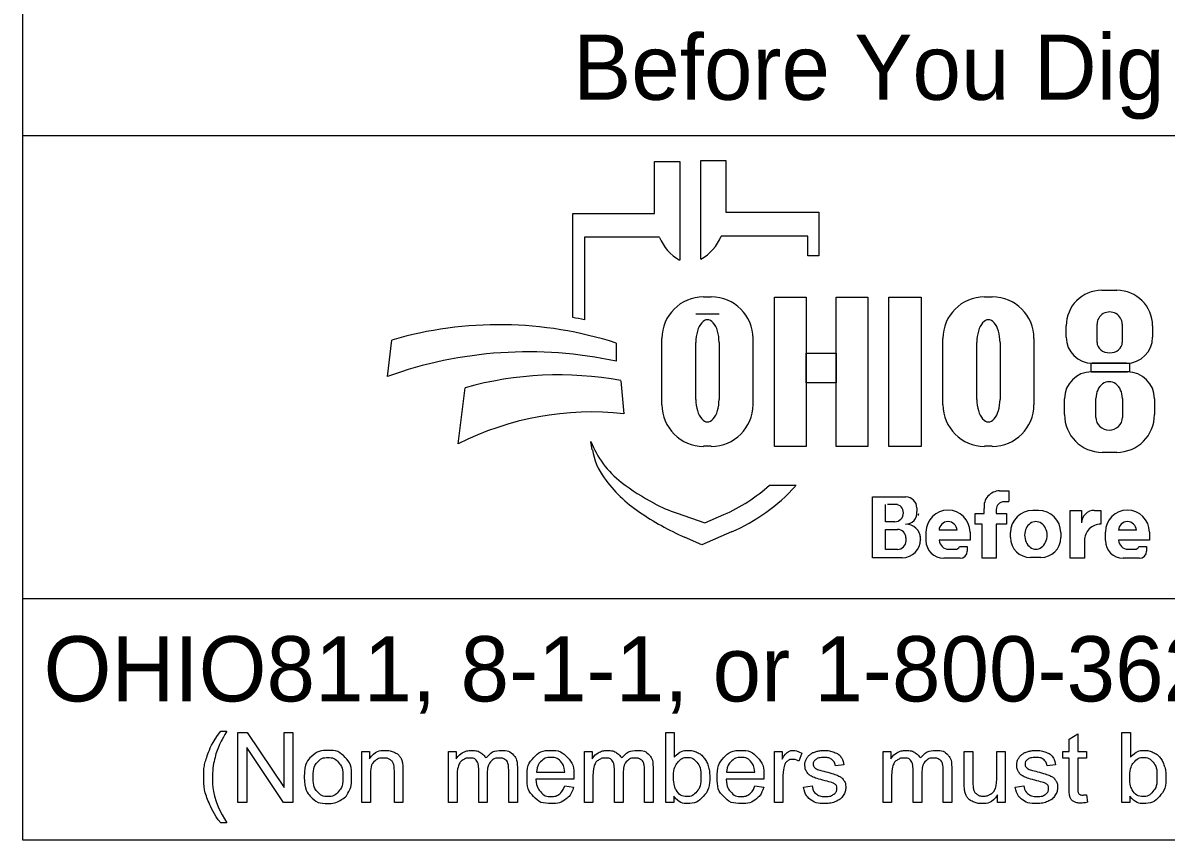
# Model space of a CAD drawing. Extents: x -10 to 89.7, y -4.8 to 22.
# Drawn here: x 2.978 to 5.431, y 2.143 to 3.897 of the extents above; entities that cross this region are included whole.
import ezdxf

# ---------------------------------------------------------------- set-up
doc = ezdxf.new("R2010")
doc.units = 0
doc.layers.add('GM_X_Minor_Lake', color=7, linetype='Continuous')
doc.layers.add('GM_X_Minor_River_Text', color=7, linetype='Continuous')

msp = doc.modelspace()

# ---------------------------------------------------------------- linework, layer by layer
at = {"layer": 'GM_X_Minor_Lake'}
for p, q in [((2.9775, 2.1428), (2.9775, 4.4803)), ((2.9775, 3.6553), (7.2275, 3.6553)), ((7.2275, 2.6607), (2.9775, 2.6607)), ((7.2275, 2.1428), (2.9775, 2.1428))]:
    msp.add_line(p, q, dxfattribs=at)
at = {"layer": 'GM_X_Minor_River_Text'}
for p, q in [((4.3335, 3.4883), (4.3335, 3.5998)), ((4.3335, 3.5998), (4.3872, 3.5998)), ((4.3872, 3.5998), (4.3872, 3.3877)), ((4.4329, 3.39), (4.4329, 3.6021)), ((4.4329, 3.6021), (4.4865, 3.6021)), ((4.4865, 3.6021), (4.4865, 3.4906)), ((4.1576, 3.2644), (4.1576, 3.4883)), ((4.1576, 3.4883), (4.3335, 3.4883)), ((4.4865, 3.4906), (4.6857, 3.4906)), ((4.6857, 3.4906), (4.6857, 3.3968)), ((4.1828, 3.4369), (4.1828, 3.26)), ((4.3439, 3.4369), (4.1828, 3.4369)), ((4.6625, 3.4392), (4.4761, 3.4392)), ((4.6625, 3.3968), (4.6625, 3.4392)), ((4.6857, 3.3968), (4.6625, 3.3968)), ((5.2931, 3.3231), (5.3258, 3.3231)), ((4.4385, 3.3091), (4.4551, 3.3091)), ((5.0416, 3.3091), (5.0581, 3.3091)), ((4.4718, 3.2721), (4.422, 3.2721)), ((5.2168, 3.2225), (5.2168, 3.2468)), ((5.283, 3.2111), (5.283, 3.2504)), ((5.3371, 3.2504), (5.3371, 3.2111)), ((5.4022, 3.2468), (5.4022, 3.2225)), ((3.7602, 3.1381), (3.7696, 3.2162)), ((4.3491, 3.0776), (4.3491, 3.2196)), ((4.5445, 3.2196), (4.5445, 3.0776)), ((4.9521, 3.0776), (4.9521, 3.2196)), ((5.1476, 3.2196), (5.1476, 3.0776)), ((4.2509, 3.2097), (4.2509, 3.1709)), ((4.422, 3.089), (4.422, 3.2114)), ((4.4718, 3.2114), (4.4718, 3.089)), ((5.025, 3.089), (5.025, 3.2114)), ((5.0748, 3.2114), (5.0748, 3.089)), ((5.3462, 3.1665), (5.2728, 3.1665)), ((5.271, 3.1482), (5.3483, 3.1482)), ((4.2608, 3.1291), (4.2671, 3.0582)), ((3.912, 2.9936), (3.9267, 3.1137)), ((5.2131, 3.0563), (5.2131, 3.0903)), ((5.2806, 3.0503), (5.2806, 3.0912)), ((5.3374, 3.0912), (5.3374, 3.0503)), ((5.4062, 3.0903), (5.4062, 3.0563)), ((4.1997, 2.9807), (4.1967, 2.9986)), ((4.4551, 2.9882), (4.4385, 2.9882)), ((5.0581, 2.9882), (5.0416, 2.9882)), ((5.3252, 2.9753), (5.2941, 2.9753)), ((4.58, 2.9048), (4.6375, 2.9048)), ((4.8013, 2.749), (4.8013, 2.8798)), ((4.8013, 2.8798), (4.8725, 2.8798)), ((5.0739, 2.8926), (5.0934, 2.8926)), ((5.0934, 2.8926), (5.0934, 2.8696)), ((4.8293, 2.8263), (4.8293, 2.8632)), ((4.8545, 2.8632), (4.8332, 2.8632)), ((4.8963, 2.856), (4.8963, 2.8481)), ((5.0406, 2.8442), (5.0406, 2.8546)), ((5.0667, 2.8526), (5.0667, 2.8442)), ((5.0934, 2.8691), (5.0832, 2.8691)), ((5.1451, 2.8508), (5.1573, 2.8508)), ((5.2254, 2.7478), (5.2254, 2.8505)), ((5.2254, 2.8505), (5.2499, 2.8505)), ((5.2499, 2.8505), (5.2499, 2.8237)), ((5.2772, 2.8505), (5.291, 2.8505)), ((5.291, 2.8505), (5.291, 2.8209)), ((4.3816, 2.8444), (4.441, 2.8239)), ((4.441, 2.8239), (4.4821, 2.8417)), ((4.8487, 2.8263), (4.8293, 2.8263)), ((5.0213, 2.8212), (5.0213, 2.8442)), ((5.0213, 2.8442), (5.0406, 2.8442)), ((5.0667, 2.8442), (5.0883, 2.8442)), ((5.0883, 2.8442), (5.0883, 2.8212)), ((4.4983, 2.8044), (4.435, 2.7769)), ((4.8293, 2.7669), (4.8293, 2.8097)), ((4.8293, 2.8097), (4.8548, 2.8097)), ((4.9159, 2.7858), (4.9159, 2.8042)), ((4.9824, 2.8082), (4.9439, 2.8082)), ((5.0104, 2.8042), (5.0104, 2.7866)), ((5.0362, 2.8212), (5.0213, 2.8212)), ((5.0362, 2.7478), (5.0362, 2.8212)), ((5.0883, 2.8212), (5.0667, 2.8212)), ((5.0667, 2.8212), (5.0667, 2.7478)), ((5.0973, 2.7922), (5.0973, 2.8029)), ((5.2051, 2.8029), (5.2051, 2.7922)), ((5.3008, 2.7858), (5.3008, 2.8042)), ((5.3674, 2.8082), (5.3288, 2.8082)), ((5.3953, 2.8042), (5.3953, 2.7866)), ((4.435, 2.7769), (4.3976, 2.7934)), ((4.8729, 2.7916), (4.8729, 2.7853)), ((4.9043, 2.7887), (4.9043, 2.7884)), ((5.0104, 2.7866), (4.944, 2.7866)), ((4.9876, 2.7729), (5.0045, 2.7729)), ((5.0045, 2.7729), (5.0045, 2.7631)), ((5.2559, 2.786), (5.2559, 2.7478)), ((5.3953, 2.7866), (5.3289, 2.7866)), ((5.3725, 2.7729), (5.3894, 2.7729)), ((5.3894, 2.7729), (5.3894, 2.7631)), ((4.865, 2.749), (4.8013, 2.749)), ((4.8546, 2.7669), (4.8293, 2.7669)), ((4.9649, 2.7673), (4.979, 2.7673)), ((5.1623, 2.7494), (5.1401, 2.7494)), ((5.3498, 2.7673), (5.3639, 2.7673)), ((4.9892, 2.7478), (4.9538, 2.7478)), ((5.0667, 2.7478), (5.0362, 2.7478)), ((5.2559, 2.7478), (5.2254, 2.7478)), ((5.3742, 2.7478), (5.3388, 2.7478))]:
    msp.add_line(p, q, dxfattribs=at)
for points in [[(4.591, 3.3081), (4.6589, 3.3081), (4.6589, 2.9881), (4.591, 2.9881)], [(4.7231, 3.3081), (4.7911, 3.3081), (4.7911, 2.9881), (4.7231, 2.9881)], [(4.8364, 3.3081), (4.9052, 3.3081), (4.9052, 2.9881), (4.8364, 2.9881)], [(4.6589, 3.1882), (4.7231, 3.1882), (4.7231, 3.1242), (4.6589, 3.1242)], [(5.2706, 3.1665), (5.3523, 3.1665), (5.3523, 3.1481), (5.2706, 3.1481)]]:
    msp.add_lwpolyline(points, close=True, dxfattribs=at)
for points in [[(3.4021, 2.3766), (3.4153, 2.3766)], [(3.4389, 2.2239), (3.4389, 2.3741), (3.4592, 2.3741), (3.5382, 2.2561), (3.5382, 2.3741), (3.5572, 2.3741), (3.5572, 2.2239), (3.5369, 2.2239), (3.4579, 2.3419), (3.4579, 2.2239), (3.4389, 2.2239)], [(4.3743, 2.2239), (4.3573, 2.2239), (4.3573, 2.3741), (4.3757, 2.3741), (4.3757, 2.3206)], [(5.2233, 2.2558), (5.2233, 2.3185), (5.2097, 2.3185), (5.2097, 2.3328), (5.2233, 2.3328), (5.2233, 2.3597), (5.2417, 2.3708), (5.2417, 2.3328), (5.2601, 2.3328), (5.2601, 2.3185), (5.2417, 2.3185), (5.2417, 2.2547)], [(5.3534, 2.2239), (5.3363, 2.2239), (5.3363, 2.3741), (5.3548, 2.3741), (5.3548, 2.3206)], [(3.7048, 2.2239), (3.7048, 2.3328), (3.7214, 2.3328), (3.7214, 2.3173)], [(3.8912, 2.2239), (3.8912, 2.3328), (3.9077, 2.3328), (3.9077, 2.3174)], [(4.1826, 2.2239), (4.1826, 2.3328), (4.1991, 2.3328), (4.1991, 2.3174)], [(4.5904, 2.2239), (4.5904, 2.3328), (4.607, 2.3328), (4.607, 2.3163)], [(4.8236, 2.2239), (4.8236, 2.3328), (4.8401, 2.3328), (4.8401, 2.3174)], [(4.9979, 2.2654), (4.9979, 2.3328), (5.0164, 2.3328), (5.0164, 2.2724)], [(5.0676, 2.2745), (5.0676, 2.3328), (5.0861, 2.3328), (5.0861, 2.2239), (5.0696, 2.2239)], [(4.6495, 2.3293), (4.643, 2.3122)], [(3.7233, 2.2833), (3.7233, 2.2239), (3.7048, 2.2239)], [(3.7932, 2.2908), (3.7932, 2.2239), (3.7748, 2.2239), (3.7748, 2.2901)], [(3.9743, 2.2871), (3.9743, 2.2239), (3.9559, 2.2239), (3.9559, 2.2946)], [(4.0388, 2.2986), (4.0388, 2.2239), (4.0203, 2.2239), (4.0203, 2.2924)], [(4.0799, 2.2887), (4.1406, 2.2887)], [(4.2657, 2.2871), (4.2657, 2.2239), (4.2473, 2.2239), (4.2473, 2.2946)], [(4.3301, 2.2986), (4.3301, 2.2239), (4.3117, 2.2239), (4.3117, 2.2924)], [(4.4879, 2.2887), (4.5486, 2.2887)], [(4.7394, 2.3046), (4.7213, 2.3022)], [(4.9067, 2.2871), (4.9067, 2.2239), (4.8883, 2.2239), (4.8883, 2.2946)], [(4.9711, 2.2986), (4.9711, 2.2239), (4.9527, 2.2239), (4.9527, 2.2924)], [(5.194, 2.3046), (5.1759, 2.3022)], [(3.9097, 2.2803), (3.9097, 2.2239), (3.8912, 2.2239)], [(4.16, 2.2736), (4.0788, 2.2736)], [(4.1404, 2.2591), (4.1595, 2.2567)], [(4.201, 2.2803), (4.201, 2.2239), (4.1826, 2.2239)], [(4.568, 2.2736), (4.4868, 2.2736)], [(4.5484, 2.2591), (4.5675, 2.2567)], [(4.6088, 2.2809), (4.6088, 2.2239), (4.5904, 2.2239)], [(4.653, 2.2564), (4.6712, 2.2593)], [(4.842, 2.2803), (4.842, 2.2239), (4.8236, 2.2239)], [(5.1076, 2.2564), (5.1258, 2.2593)], [(4.3743, 2.2375), (4.3743, 2.2239)], [(5.0696, 2.2239), (5.0696, 2.24)], [(5.2601, 2.2404), (5.2628, 2.2241)], [(5.3534, 2.2375), (5.3534, 2.2239)], [(3.4153, 2.1798), (3.4021, 2.1798)]]:
    msp.add_lwpolyline(points, dxfattribs=at)
for centre, radius, start, end in [((4.4353, 3.4736), 0.0985, 201.9296, 240.7469), ((4.3847, 3.476), 0.0985, 299.2531, 338.0704), ((5.2931, 3.2468), 0.0763, 90, 180), ((5.3258, 3.2468), 0.0763, 0, 90), ((4.4385, 3.2196), 0.0895, 90, 180), ((4.4551, 3.2196), 0.0895, 0, 90), ((5.0416, 3.2196), 0.0895, 90, 180), ((5.0581, 3.2196), 0.0895, 0, 90), ((4.0295, 2.4554), 0.8191, 79.2074, 81.0007), ((3.9997, 2.4302), 0.8191, 72.1402, 106.3144), ((5.2728, 3.2225), 0.056, 180, 270), ((5.3462, 3.2225), 0.056, 270, 0), ((4.0628, 2.2991), 0.8919, 77.8238, 109.8274), ((4.1267, 2.4094), 0.7322, 79.44, 105.8467), ((5.271, 3.0903), 0.0579, 90, 180), ((5.3483, 3.0903), 0.0579, 0, 90), ((4.4385, 3.0776), 0.0895, 180, 270), ((4.4551, 3.0776), 0.0895, 270, 0), ((5.0416, 3.0776), 0.0895, 180, 270), ((5.0581, 3.0776), 0.0895, 270, 0), ((4.1987, 2.4262), 0.6357, 83.8248, 116.8021), ((5.2941, 3.0563), 0.081, 180, 270), ((5.3252, 3.0563), 0.081, 270, 0), ((4.3841, 3.0707), 0.2008, 201.0457, 232.5314), ((4.341, 3.0048), 0.1433, 189.6817, 216.0884), ((4.4747, 3.1022), 0.3088, 216.0884, 235.7167), ((4.5766, 3.3219), 0.5173, 232.5314, 241.794), ((4.3387, 3.1722), 0.3602, 293.4582, 312.0712), ((4.3387, 3.1722), 0.401, 293.4582, 317.8286), ((4.8725, 2.856), 0.0238, 0, 90), ((5.0739, 2.859), 0.0335, 90, 187.5187), ((4.6412, 3.3465), 0.6044, 235.7167, 246.2325), ((4.4914, 3.1631), 0.3371, 241.794, 250.9821), ((4.8505, 2.8463), 0.0169, 357.8325, 90), ((4.8721, 2.8453), 0.0243, 270, 6.6529), ((4.9631, 2.8042), 0.0473, 0, 180), ((5.0832, 2.8526), 0.0165, 90, 180), ((5.1451, 2.8029), 0.0478, 90, 180), ((5.1573, 2.8029), 0.0478, 0, 90), ((5.2768, 2.8237), 0.0269, 89.2449, 180), ((5.3481, 2.8042), 0.0473, 0, 180), ((4.8487, 2.845), 0.0187, 270, 2.0582), ((4.8827, 2.8438), 0.0175, 347.4023, 0), ((4.9632, 2.8072), 0.0193, 2.9632, 177.0368), ((5.3481, 2.8072), 0.0193, 2.9632, 177.0368), ((4.8548, 2.7916), 0.0181, 0, 90), ((4.8722, 2.7889), 0.0321, 4.0748, 90), ((5.2908, 2.786), 0.0349, 89.6033, 180), ((4.8546, 2.7853), 0.0184, 270, 0), ((4.865, 2.7884), 0.0393, 270, 0), ((4.8714, 2.7887), 0.033, 0, 11.7502), ((4.9538, 2.7858), 0.038, 180, 270), ((4.9649, 2.7883), 0.021, 184.827, 270), ((4.979, 2.7767), 0.00938, 270, 335.9979), ((5.1401, 2.7922), 0.0428, 180, 270), ((5.1623, 2.7922), 0.0428, 270, 0), ((5.3388, 2.7858), 0.038, 180, 270), ((5.3498, 2.7883), 0.021, 184.827, 270), ((5.3639, 2.7767), 0.00938, 270, 335.9979), ((4.9892, 2.7631), 0.0152, 270, 0), ((5.3742, 2.7631), 0.0152, 270, 0)]:
    msp.add_arc(centre, radius, start, end, dxfattribs=at)
for centre, major_axis, ratio, start_param, end_param in [((5.31, 3.2504), (0.0271, 0), 0.969373, 0, 3.141593), ((4.4469, 3.2114), (0, 0.0484), 0.514403, 4.712389, 7.853982), ((5.0499, 3.2114), (0, 0.0484), 0.514403, 4.712389, 7.853982), ((5.31, 3.2111), (0.0271, 0), 0.818453, 3.141593, 6.283185), ((5.309, 3.0912), (0, 0.0358), 0.794529, 4.712389, 7.853982), ((4.4469, 3.089), (0, 0.0484), 0.514403, 1.570796, 4.712389), ((5.0499, 3.089), (0, 0.0484), 0.514403, 1.570796, 4.712389), ((5.309, 3.0503), (0.0284, 0), 0.959837, 3.141593, 6.283185), ((5.1517, 2.7976), (0, 0.029), 0.832186, 4.712389, 7.853982), ((5.1517, 2.7976), (0, 0.0302), 0.797287, 1.570796, 4.712389)]:
    msp.add_ellipse(centre, major_axis=major_axis, ratio=ratio, start_param=start_param, end_param=end_param, dxfattribs=at)
for points in [[(3.4021, 2.1798), (3.3869, 2.199), (3.3763, 2.2248), (3.3657, 2.2506), (3.3657, 2.2783), (3.3657, 2.3026), (3.3736, 2.325), (3.3829, 2.3509), (3.4021, 2.3766)], [(3.4153, 2.3766), (3.4029, 2.3553), (3.3989, 2.3462), (3.3927, 2.332), (3.3891, 2.3167), (3.3847, 2.2975), (3.3847, 2.2782), (3.3847, 2.2289), (3.4153, 2.1798)], [(3.5814, 2.2783), (3.5814, 2.3085), (3.5981, 2.3231), (3.6122, 2.3352), (3.6323, 2.3352), (3.6547, 2.3352), (3.669, 2.3205), (3.6832, 2.3058), (3.6832, 2.2799), (3.6832, 2.2589), (3.6769, 2.2469), (3.6706, 2.2348), (3.6586, 2.2282), (3.6466, 2.2215), (3.6323, 2.2215), (3.6095, 2.2215), (3.5954, 2.2362), (3.5814, 2.2508), (3.5814, 2.2783)], [(3.7214, 2.3173), (3.7334, 2.3352), (3.756, 2.3352), (3.7659, 2.3352), (3.7741, 2.3316), (3.7823, 2.3281), (3.7864, 2.3224), (3.7905, 2.3166), (3.7922, 2.3087), (3.7932, 2.3036), (3.7932, 2.2908)], [(3.9077, 2.3174), (3.9128, 2.3254), (3.9214, 2.3303), (3.9299, 2.3352), (3.9407, 2.3352), (3.9528, 2.3352), (3.9606, 2.3301), (3.9683, 2.3251), (3.9715, 2.3161), (3.9844, 2.3352), (4.0051, 2.3352), (4.0213, 2.3352), (4.03, 2.3262), (4.0388, 2.3172), (4.0388, 2.2986)], [(4.1595, 2.2567), (4.155, 2.24), (4.1428, 2.2307), (4.1306, 2.2215), (4.1117, 2.2215), (4.0878, 2.2215), (4.0738, 2.2362), (4.0598, 2.2509), (4.0598, 2.2774), (4.0598, 2.3049), (4.074, 2.32), (4.0881, 2.3352), (4.1106, 2.3352), (4.1324, 2.3352), (4.1463, 2.3203), (4.1601, 2.3055), (4.1601, 2.2785), (4.1601, 2.2769), (4.16, 2.2736)], [(4.1991, 2.3174), (4.2042, 2.3254), (4.2127, 2.3303), (4.2212, 2.3352), (4.2321, 2.3352), (4.2442, 2.3352), (4.2519, 2.3301), (4.2597, 2.3251), (4.2628, 2.3161), (4.2758, 2.3352), (4.2965, 2.3352), (4.3127, 2.3352), (4.3214, 2.3262), (4.3301, 2.3172), (4.3301, 2.2986)], [(4.3757, 2.3206), (4.3874, 2.3352), (4.4055, 2.3352), (4.4155, 2.3352), (4.4245, 2.3311), (4.4335, 2.3271), (4.4392, 2.3198), (4.445, 2.3124), (4.4483, 2.3021), (4.4516, 2.2918), (4.4516, 2.28), (4.4516, 2.252), (4.4378, 2.2368), (4.4239, 2.2215), (4.4046, 2.2215), (4.3853, 2.2215), (4.3743, 2.2375)], [(4.5675, 2.2567), (4.563, 2.24), (4.5508, 2.2307), (4.5386, 2.2215), (4.5196, 2.2215), (4.4958, 2.2215), (4.4818, 2.2362), (4.4678, 2.2509), (4.4678, 2.2774), (4.4678, 2.3049), (4.482, 2.32), (4.4961, 2.3352), (4.5186, 2.3352), (4.5404, 2.3352), (4.5543, 2.3203), (4.5681, 2.3055), (4.5681, 2.2785), (4.5681, 2.2769), (4.568, 2.2736)], [(4.607, 2.3163), (4.6133, 2.3278), (4.6187, 2.3315), (4.6241, 2.3352), (4.6305, 2.3352), (4.6398, 2.3352), (4.6495, 2.3293)], [(4.6712, 2.2593), (4.6727, 2.2483), (4.6798, 2.2425), (4.6868, 2.2366), (4.6995, 2.2366), (4.7122, 2.2366), (4.7184, 2.2418), (4.7245, 2.247), (4.7245, 2.254), (4.7245, 2.2602), (4.7191, 2.2638), (4.7153, 2.2663), (4.7002, 2.2701), (4.6799, 2.2752), (4.672, 2.2789), (4.6642, 2.2827), (4.6601, 2.2893), (4.6561, 2.2959), (4.6561, 2.3038), (4.6561, 2.3111), (4.6594, 2.3173), (4.6628, 2.3235), (4.6685, 2.3276), (4.6728, 2.3308), (4.6803, 2.333), (4.6877, 2.3352), (4.6962, 2.3352), (4.709, 2.3352), (4.7187, 2.3315), (4.7284, 2.3278), (4.733, 2.3215), (4.7377, 2.3152), (4.7394, 2.3046)], [(4.8401, 2.3174), (4.8452, 2.3254), (4.8537, 2.3303), (4.8622, 2.3352), (4.8731, 2.3352), (4.8852, 2.3352), (4.8929, 2.3301), (4.9007, 2.3251), (4.9038, 2.3161), (4.9168, 2.3352), (4.9375, 2.3352), (4.9537, 2.3352), (4.9624, 2.3262), (4.9711, 2.3172), (4.9711, 2.2986)], [(5.1258, 2.2593), (5.1273, 2.2483), (5.1343, 2.2425), (5.1414, 2.2366), (5.154, 2.2366), (5.1668, 2.2366), (5.1729, 2.2418), (5.1791, 2.247), (5.1791, 2.254), (5.1791, 2.2602), (5.1736, 2.2638), (5.1698, 2.2663), (5.1548, 2.2701), (5.1345, 2.2752), (5.1266, 2.2789), (5.1188, 2.2827), (5.1147, 2.2893), (5.1107, 2.2959), (5.1107, 2.3038), (5.1107, 2.3111), (5.114, 2.3173), (5.1173, 2.3235), (5.1231, 2.3276), (5.1274, 2.3308), (5.1348, 2.333), (5.1423, 2.3352), (5.1508, 2.3352), (5.1636, 2.3352), (5.1733, 2.3315), (5.183, 2.3278), (5.1876, 2.3215), (5.1922, 2.3152), (5.194, 2.3046)], [(5.3548, 2.3206), (5.3664, 2.3352), (5.3846, 2.3352), (5.3946, 2.3352), (5.4036, 2.3311), (5.4125, 2.3271), (5.4183, 2.3198), (5.4241, 2.3124), (5.4274, 2.3021), (5.4306, 2.2918), (5.4306, 2.28), (5.4306, 2.252), (5.4168, 2.2368), (5.403, 2.2215), (5.3836, 2.2215), (5.3644, 2.2215), (5.3534, 2.2375)], [(3.6003, 2.2783), (3.6003, 2.2574), (3.6094, 2.247), (3.6185, 2.2366), (3.6323, 2.2366), (3.646, 2.2366), (3.6551, 2.2471), (3.6642, 2.2575), (3.6642, 2.279), (3.6642, 2.2991), (3.6551, 2.3095), (3.6459, 2.3199), (3.6323, 2.3199), (3.6185, 2.3199), (3.6094, 2.3096), (3.6003, 2.2992), (3.6003, 2.2783)], [(3.7748, 2.2901), (3.7748, 2.3013), (3.7726, 2.3069), (3.7705, 2.3125), (3.765, 2.3158), (3.7595, 2.3191), (3.7521, 2.3191), (3.7404, 2.3191), (3.7318, 2.3117), (3.7233, 2.3042), (3.7233, 2.2833)], [(3.9559, 2.2946), (3.9559, 2.3069), (3.9514, 2.313), (3.9469, 2.3191), (3.9366, 2.3191), (3.9288, 2.3191), (3.9222, 2.315), (3.9156, 2.311), (3.9126, 2.3031), (3.9097, 2.2952), (3.9097, 2.2803)], [(4.0203, 2.2924), (4.0203, 2.3035), (4.0185, 2.3083), (4.0168, 2.3132), (4.012, 2.3162), (4.0073, 2.3191), (4.001, 2.3191), (3.9895, 2.3191), (3.9819, 2.3115), (3.9743, 2.3039), (3.9743, 2.2871)], [(4.1406, 2.2887), (4.1394, 2.3025), (4.1337, 2.3094), (4.1249, 2.3201), (4.1108, 2.3201), (4.0981, 2.3201), (4.0894, 2.3115), (4.0808, 2.303), (4.0799, 2.2887)], [(4.2473, 2.2946), (4.2473, 2.3069), (4.2428, 2.313), (4.2383, 2.3191), (4.228, 2.3191), (4.2202, 2.3191), (4.2136, 2.315), (4.207, 2.311), (4.204, 2.3031), (4.201, 2.2952), (4.201, 2.2803)], [(4.3117, 2.2924), (4.3117, 2.3035), (4.3099, 2.3083), (4.3081, 2.3132), (4.3034, 2.3162), (4.2987, 2.3191), (4.2923, 2.3191), (4.2809, 2.3191), (4.2733, 2.3115), (4.2657, 2.3039), (4.2657, 2.2871)], [(4.3741, 2.2792), (4.3741, 2.2596), (4.3794, 2.2509), (4.3881, 2.2366), (4.4029, 2.2366), (4.415, 2.2366), (4.4238, 2.2471), (4.4326, 2.2576), (4.4326, 2.2784), (4.4326, 2.2998), (4.4241, 2.3099), (4.4157, 2.3201), (4.4038, 2.3201), (4.3917, 2.3201), (4.3829, 2.3096), (4.3741, 2.299), (4.3741, 2.2792)], [(4.5486, 2.2887), (4.5474, 2.3025), (4.5417, 2.3094), (4.5328, 2.3201), (4.5188, 2.3201), (4.5061, 2.3201), (4.4974, 2.3115), (4.4888, 2.303), (4.4879, 2.2887)], [(4.643, 2.3122), (4.6363, 2.3162), (4.6295, 2.3162), (4.6235, 2.3162), (4.6187, 2.3125), (4.6139, 2.3089), (4.6119, 2.3024), (4.6088, 2.2926), (4.6088, 2.2809)], [(4.7213, 2.3022), (4.7201, 2.3106), (4.7142, 2.3153), (4.7083, 2.3201), (4.6975, 2.3201), (4.6848, 2.3201), (4.6794, 2.3159), (4.6739, 2.3116), (4.6739, 2.306), (4.6739, 2.3024), (4.6762, 2.2995), (4.6785, 2.2966), (4.6833, 2.2946), (4.686, 2.2936), (4.6996, 2.2899), (4.7192, 2.2847), (4.7269, 2.2813), (4.7347, 2.278), (4.7391, 2.2717), (4.7435, 2.2653), (4.7435, 2.2559), (4.7435, 2.2467), (4.7381, 2.2386), (4.7327, 2.2304), (4.7226, 2.226), (4.7124, 2.2215), (4.6996, 2.2215), (4.6784, 2.2215), (4.6672, 2.2303), (4.6561, 2.2391), (4.653, 2.2564)], [(4.8883, 2.2946), (4.8883, 2.3069), (4.8838, 2.313), (4.8793, 2.3191), (4.869, 2.3191), (4.8612, 2.3191), (4.8546, 2.315), (4.848, 2.311), (4.845, 2.3031), (4.842, 2.2952), (4.842, 2.2803)], [(4.9527, 2.2924), (4.9527, 2.3035), (4.9509, 2.3083), (4.9491, 2.3132), (4.9444, 2.3162), (4.9397, 2.3191), (4.9333, 2.3191), (4.9219, 2.3191), (4.9143, 2.3115), (4.9067, 2.3039), (4.9067, 2.2871)], [(5.1759, 2.3022), (5.1747, 2.3106), (5.1688, 2.3153), (5.1629, 2.3201), (5.1521, 2.3201), (5.1394, 2.3201), (5.1339, 2.3159), (5.1285, 2.3116), (5.1285, 2.306), (5.1285, 2.3024), (5.1308, 2.2995), (5.133, 2.2966), (5.1378, 2.2946), (5.1406, 2.2936), (5.1542, 2.2899), (5.1737, 2.2847), (5.1815, 2.2813), (5.1893, 2.278), (5.1937, 2.2717), (5.1981, 2.2653), (5.1981, 2.2559), (5.1981, 2.2467), (5.1927, 2.2386), (5.1873, 2.2304), (5.1772, 2.226), (5.167, 2.2215), (5.1542, 2.2215), (5.1329, 2.2215), (5.1218, 2.2303), (5.1107, 2.2391), (5.1076, 2.2564)], [(5.3532, 2.2792), (5.3532, 2.2596), (5.3585, 2.2509), (5.3672, 2.2366), (5.382, 2.2366), (5.3941, 2.2366), (5.4029, 2.2471), (5.4116, 2.2576), (5.4116, 2.2784), (5.4116, 2.2998), (5.4032, 2.3099), (5.3948, 2.3201), (5.3828, 2.3201), (5.3708, 2.3201), (5.362, 2.3096), (5.3532, 2.299), (5.3532, 2.2792)], [(4.0788, 2.2736), (4.0799, 2.2557), (4.089, 2.2462), (4.0981, 2.2366), (4.1117, 2.2366), (4.1219, 2.2366), (4.1291, 2.242), (4.1362, 2.2473), (4.1404, 2.2591)], [(4.4868, 2.2736), (4.4879, 2.2557), (4.497, 2.2462), (4.5061, 2.2366), (4.5197, 2.2366), (4.5299, 2.2366), (4.537, 2.242), (4.5442, 2.2473), (4.5484, 2.2591)], [(5.0696, 2.24), (5.0569, 2.2215), (5.0351, 2.2215), (5.0255, 2.2215), (5.0171, 2.2252), (5.0088, 2.2289), (5.0047, 2.2345), (5.0007, 2.2401), (4.9991, 2.2482), (4.9979, 2.2536), (4.9979, 2.2654)], [(5.0164, 2.2724), (5.0164, 2.258), (5.0175, 2.253), (5.0192, 2.2457), (5.0249, 2.2416), (5.0305, 2.2374), (5.0388, 2.2374), (5.0471, 2.2374), (5.0543, 2.2417), (5.0616, 2.2459), (5.0646, 2.2533), (5.0676, 2.2606), (5.0676, 2.2745)], [(5.2628, 2.2241), (5.255, 2.2224), (5.2488, 2.2224), (5.2388, 2.2224), (5.2333, 2.2256), (5.2278, 2.2288), (5.2255, 2.234), (5.2233, 2.2392), (5.2233, 2.2558)], [(5.2417, 2.2547), (5.2417, 2.2468), (5.2427, 2.2445), (5.2436, 2.2423), (5.2458, 2.2409), (5.248, 2.2396), (5.2521, 2.2396), (5.2551, 2.2396), (5.2601, 2.2404)]]:
    msp.add_open_spline(points, degree=3, dxfattribs=at)

# ---------------------------------------------------------------- texts
for s, p in [('Before You Dig', (4.1583, 3.7321)), ('OHIO811, 8-1-1, or 1-800-362-2764', (3.022, 2.4406))]:
    msp.add_text(s, height=0.14, dxfattribs=at).set_placement(p)

doc.saveas('drawing.dxf')
